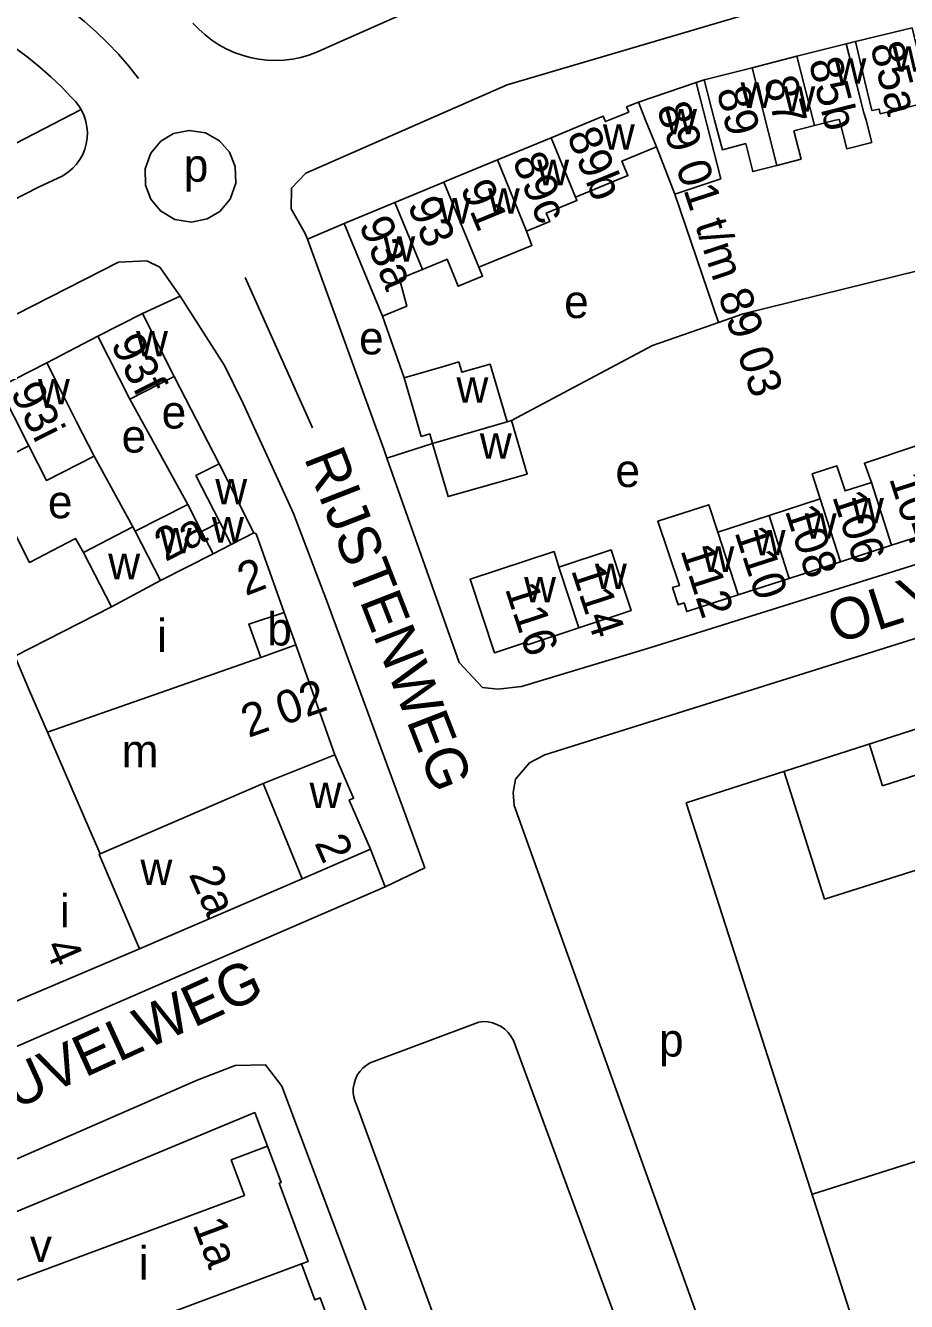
# Model space of a CAD drawing. Extents: x 157569 to 159501, y 382907 to 384670.
# Drawn here: x 158949.1 to 159055.8, y 383107 to 383261.5 of the extents above; entities that cross this region are included whole.
import ezdxf

# ---------------------------------------------------------------- set-up
doc = ezdxf.new("R2010")
doc.units = 0
for name, color, linetype in [('BLT_Basislijn', 7, 'Continuous'), ('BLT_Bebouwing', 7, 'Continuous'), ('BLT_Centroide', 7, 'Continuous'), ('BLT_Huisnummer', 7, 'Continuous'), ('BLT_Huisnummer_ tussenligend', 7, 'Continuous'), ('BLT_Huisnummer_reeks', 7, 'Continuous'), ('BLT_Onderverdeling_panden', 7, 'Continuous'), ('BLT_Straatnaam', 7, 'Continuous')]:
    doc.layers.add(name, color=color, linetype=linetype)

msp = doc.modelspace()

# ---------------------------------------------------------------- linework, layer by layer
at = {"layer": 'BLT_Basislijn'}
for p, q in [((158986.46, 383259.17), (158984.48, 383258.27)), ((159048.48, 383259.25), (159049.59, 383259.54)), ((159031.29, 383254.88), (159030.3, 383254.58)), ((158942.87, 383244.6), (158955.85, 383251.29)), ((158953.54, 383243.23), (158950.69, 383241.92)), ((159027.72, 383241.05), (159033.01, 383225.51)), ((158983.24, 383235.61), (158987.69, 383237.51)), ((158975.72, 383230.98), (158983.87, 383212.76)), ((158992.34, 383226.28), (158994.96, 383218.81)), ((158957.88, 383223.88), (158951.69, 383220.63)), ((158972.58, 383208.41), (158967.13, 383218.98)), ((158968.75, 383203.51), (158961.74, 383216.25)), ((158998.41, 383210.87), (158992.86, 383209.11)), ((158957.41, 383209.34), (158962.13, 383200.77)), ((159052.86, 383169.46), (159051.28, 383174.44)), ((159052.86, 383169.46), (159065.74, 383173.54)), ((159045.86, 383155.71), (159040.97, 383171.13)), ((159045.86, 383155.71), (159057.84, 383159.51)), ((158990.86, 383135.91), (159003.99, 383140.85)), ((159008.19, 383138.62), (159052.52, 383018.25)), ((159032.62, 383012.27), (158989.29, 383130.64)), ((159044.4, 383120.03), (159066.26, 383126.96))]:
    msp.add_line(p, q, dxfattribs=at)
for points in [[(158983.24, 383235.61), (158982.98, 383236.31), (158981.28, 383239.26), (158981.31, 383241.77), (158983.04, 383243.59), (159007.41, 383254.28), (159036.07, 383262.73), (159100, 383276.35), (159146.03, 383286.21), (159155.39, 383288.52), (159181.52, 383295.52), (159205.36, 383303.77), (159241.92, 383319.57), (159301.34, 383349.43)], [(159258.99, 383340.92), (159227.33, 383325.46), (159190.02, 383310.81), (159165.47, 383303.18), (159141.61, 383297.45), (159119.64, 383292.64), (159100, 383288.81), (159051.92, 383279.92), (159027.35, 383274.07), (158997.57, 383264.08), (158986.46, 383259.17)], [(158962.81, 383255.07), (158961.61, 383256.56), (158960.36, 383257.99), (158959.05, 383259.37), (158957.67, 383260.7), (158956.25, 383261.97), (158954.77, 383263.17), (158953.24, 383264.32), (158951.67, 383265.39), (158950.06, 383266.4), (158948.4, 383267.35), (158946.7, 383268.22), (158944.97, 383269.02), (158943.21, 383269.74), (158941.42, 383270.4), (158939.6, 383270.97), (158938.1, 383271.39)], [(158954.68, 383252.76), (158953.46, 383254.04), (158952.19, 383255.27), (158950.87, 383256.43), (158949.49, 383257.54), (158948.06, 383258.59), (158946.59, 383259.56), (158945.08, 383260.47), (158943.52, 383261.32), (158941.93, 383262.08), (158940.31, 383262.78), (158938.66, 383263.4), (158938.35, 383263.51)], [(158969.39, 383261.76), (158970.1, 383261.01), (158970.86, 383260.32), (158971.67, 383259.69), (158972.53, 383259.13), (158973.43, 383258.63), (158974.37, 383258.21), (158975.34, 383257.86), (158976.33, 383257.59), (158977.34, 383257.39), (158978.36, 383257.27), (158979.39, 383257.24), (158980.41, 383257.28), (158981.43, 383257.4), (158982.44, 383257.6), (158983.43, 383257.88), (158984.48, 383258.27)], [(158954.68, 383252.76), (158955.16, 383252.27), (158955.58, 383251.73), (158955.85, 383251.29)], [(158955.85, 383251.29), (158955.93, 383251.14), (158956.22, 383250.52), (158956.43, 383249.86), (158956.56, 383249.19), (158956.61, 383248.51), (158956.59, 383247.82), (158956.48, 383247.15), (158956.3, 383246.49), (158956.04, 383245.85), (158955.7, 383245.25), (158955.3, 383244.7), (158954.84, 383244.19), (158954.32, 383243.74), (158953.76, 383243.35), (158953.54, 383243.23)], [(158964.28, 383240.45), (158963.64, 383242.16), (158963.61, 383244.13), (158964.29, 383246.01), (158965.52, 383247.47), (158967.05, 383248.38), (158968.92, 383248.76), (158970.9, 383248.46), (158972.62, 383247.49), (158973.82, 383246.12)], [(158973.82, 383246.12), (158974.51, 383244.4), (158974.57, 383242.39), (158973.9, 383240.46), (158972.66, 383238.97), (158971.11, 383238.05), (158969.2, 383237.67), (158967.19, 383238), (158965.46, 383239.02), (158964.28, 383240.45)], [(158950.69, 383241.92), (158900.38, 383216.18), (158872.67, 383201.63), (158869.57, 383201.4), (158867.85, 383201.97), (158865.45, 383204.11), (158860.24, 383214.9), (158860.73, 383216.37)], [(158992.86, 383209.11), (158992.49, 383210.17), (158983.24, 383235.61)], [(159033.01, 383225.51), (159036.02, 383226.55), (159069.54, 383234.85), (159071.6, 383228.57)], [(158713.92, 383128.64), (158712.94, 383133.49), (158714.96, 383135.61), (158716, 383136.04), (158726.81, 383137.39), (158746.81, 383140.46), (158763.56, 383144.53), (158777.06, 383148.27), (158789.46, 383152.3), (158807.27, 383158.8), (158820.57, 383164.35), (158834.91, 383169.88), (158851.49, 383178.15), (158858.84, 383181.12), (158960.36, 383232.84), (158963.81, 383232.99), (158965.38, 383232.2), (158967.85, 383228.7)], [(158967.85, 383228.7), (158963.27, 383226.61)], [(158967.85, 383228.7), (158973.19, 383220.33), (158975.44, 383215.8), (158979.89, 383206.05), (158981.58, 383202.4), (158985.54, 383191.9), (158994.7, 383167.01), (158997.45, 383159.51), (158992.66, 383157.23)], [(159033.01, 383225.51), (159031.54, 383225), (159025.01, 383222.72), (159007.97, 383213.64)], [(158992.86, 383209.11), (159001.6, 383184.37), (159004.46, 383181.35), (159006.29, 383181.14), (159009.17, 383181.46), (159024.84, 383186.18), (159079.71, 383203.39)], [(158956.15, 383197.7), (158955.15, 383199.38), (158949.59, 383196.49), (158943.86, 383207.72)], [(159095.76, 383199.49), (159012.01, 383173.2), (159010.9, 383172.61)], [(159056.81, 383032.3), (159050.6, 383048.46), (159049.9, 383051.11), (159008.27, 383167.05), (159008.15, 383168.62), (159008.43, 383170.26), (159010.15, 383172.21), (159010.9, 383172.61)], [(158992.66, 383157.23), (158990.89, 383161.78)], [(158798.88, 383067.54), (158806.29, 383075.44), (158812.08, 383078.95), (158826.96, 383085.41), (158855.36, 383097.72), (158904.77, 383119.14), (158965.12, 383145.3), (158992.66, 383157.23)], [(159003.99, 383140.85), (159004.55, 383140.9), (159005.11, 383140.86), (159005.66, 383140.75), (159006.19, 383140.57), (159006.69, 383140.31), (159007.14, 383139.98), (159007.55, 383139.59), (159007.89, 383139.14), (159008.19, 383138.62)], [(158936.77, 383119.38), (158969.88, 383133.81), (158974.51, 383135.58), (158978.18, 383135.67), (158980.16, 383133.11), (159017.03, 383034.98), (159017.34, 383033.57), (159025.08, 383013.6), (159026.48, 383010.61), (159027.89, 383004.66), (159027.89, 382995.94), (159019.93, 382958.95)], [(158990.86, 383135.91), (158990.39, 383135.63), (158989.96, 383135.28), (158989.59, 383134.87), (158989.28, 383134.41), (158989.05, 383133.92), (158988.89, 383133.39), (158988.8, 383132.85), (158988.8, 383132.3), (158988.87, 383131.75), (158989.02, 383131.22), (158989.29, 383130.64)], [(158978.43, 383125.82), (158976.88, 383129.89), (158938.9, 383114.12)]]:
    msp.add_lwpolyline(points, dxfattribs=at)
msp.add_lwpolyline([(159029.12, 383167.37), (159059.9, 383071.66), (159120.99, 383091.31), (159090.21, 383187.01)], close=True, dxfattribs=at)
at = {"layer": 'BLT_Bebouwing'}
for p, q in [((159056.47, 383261.17), (159049.59, 383259.54)), ((159048.48, 383259.25), (159042.51, 383257.74)), ((159042.51, 383257.74), (159037.08, 383256.36)), ((159037.08, 383256.36), (159031.29, 383254.88)), ((159023.31, 383252.19), (159030.3, 383254.58)), ((159012.74, 383247.88), (159006.24, 383245.19)), ((159027.72, 383241.05), (159025.5, 383246.77)), ((158993.83, 383240.05), (158999.77, 383242.51)), ((158987.69, 383237.51), (158993.83, 383240.05)), ((158992.34, 383226.28), (158987.69, 383237.51)), ((158957.88, 383223.88), (158963.27, 383226.61)), ((158963.27, 383226.61), (158967.13, 383218.98)), ((158961.74, 383216.25), (158957.88, 383223.88)), ((158951.69, 383220.63), (158945.9, 383217.7)), ((158967.13, 383218.98), (158961.74, 383216.25)), ((158996.21, 383214.55), (158994.96, 383218.81)), ((158955.29, 383213.51), (158957.41, 383209.34)), ((159007.42, 383213.48), (159007.97, 383213.64)), ((158949.52, 383210.59), (158943.86, 383207.72)), ((158972.58, 383208.41), (158976.75, 383200.05)), ((159045.32, 383204.16), (159039.13, 383202.15)), ((159039.13, 383202.15), (159032.93, 383200.14)), ((158962.13, 383200.77), (158956.15, 383197.7)), ((158962.39, 383200.28), (158962.13, 383200.77)), ((159060.18, 383200.58), (159053.98, 383198.57)), ((159053.98, 383198.57), (159047.78, 383196.56)), ((158956.15, 383197.7), (158959.54, 383191.09)), ((159047.78, 383196.56), (159041.59, 383194.55)), ((159041.59, 383194.55), (159035.39, 383192.55)), ((158980.42, 383190.43), (158981.83, 383186.5)), ((158986.55, 383173.21), (158981.83, 383186.5)), ((158982.61, 383158.19), (158962.93, 383149.7))]:
    msp.add_line(p, q, dxfattribs=at)
for points in [[(159049.59, 383259.54), (159050.75, 383254.67), (159051.59, 383251.16), (159052.45, 383251.36), (159052.59, 383250.78), (159058.6, 383252.21), (159057.63, 383256.3), (159056.47, 383261.17)], [(159044.64, 383249.36), (159047.2, 383250), (159047.62, 383250.1), (159047.67, 383250), (159048.55, 383246.54), (159051.57, 383247.31), (159050.91, 383250), (159050.62, 383250.9), (159049.71, 383254.41), (159048.48, 383259.25)], [(159030.3, 383254.58), (159033.28, 383242.92), (159027.72, 383241.05)], [(159031.29, 383254.88), (159032.53, 383250), (159033.48, 383246.43), (159036.31, 383247.17), (159037.16, 383243.79), (159040.09, 383244.53)], [(159023.31, 383252.19), (159021.89, 383251.61), (159022.15, 383250.99), (159019.73, 383250), (159019.33, 383249.84), (159019.26, 383250), (159019.07, 383250.49), (159017.87, 383250), (159012.74, 383247.88)], [(159040.09, 383244.53), (159043.02, 383245.28), (159042.14, 383248.73), (159044.64, 383249.36)], [(159015.71, 383240.68), (159022.05, 383243.3), (159021.33, 383245.05), (159025.5, 383246.77)], [(158999.77, 383242.51), (159000, 383242.61), (159006.24, 383245.19)], [(159009.78, 383236.58), (159012.59, 383237.73), (159012.17, 383238.75), (159015.88, 383240.27), (159015.71, 383240.68)], [(159004.01, 383232.21), (159010.42, 383234.85), (159009.78, 383236.58)], [(158997.19, 383231.95), (159000, 383233.11), (159000.15, 383233.17), (159001.5, 383229.91), (159004.46, 383231.13), (159004.01, 383232.21)], [(158997.19, 383231.95), (158994.4, 383230.79), (158995.27, 383227.49), (158992.34, 383226.28)], [(158955.29, 383213.51), (158953.95, 383216.17), (158951.69, 383220.63)], [(158994.96, 383218.81), (159000, 383220.28), (159001.56, 383220.74), (159001.93, 383219.49), (159005.37, 383220.49), (159007.42, 383213.48)], [(158998.41, 383210.87), (158998.06, 383212.03), (158997.03, 383211.73), (158996.21, 383214.55)], [(159007.97, 383213.64), (159009.84, 383207.18), (159000.28, 383204.45), (159000, 383205.43), (158998.41, 383210.87)], [(158957.41, 383209.34), (158951.64, 383206.41), (158949.52, 383210.59)], [(159057, 383210.39), (159056.93, 383210.58), (159050.69, 383208.49), (159051.52, 383206.17)], [(158972.63, 383201.36), (158969.74, 383207), (158972.58, 383208.41)], [(159051.52, 383206.17), (159048.34, 383205.14), (159047.36, 383208.17), (159044.36, 383207.2), (159045.32, 383204.16)], [(158962.39, 383200.28), (158968.75, 383203.51)], [(158968.75, 383203.51), (158970.44, 383200.22)], [(159035.39, 383192.55), (159029.2, 383190.54), (159028.86, 383191.59), (159028.12, 383191.35), (159027.45, 383193.43), (159028.28, 383193.7), (159025.66, 383201.47), (159031.83, 383203.46), (159032.93, 383200.14)], [(158970.44, 383200.22), (158972.63, 383201.36)], [(158976.75, 383200.05), (158977.03, 383199.94), (158980.42, 383190.43)], [(159016.12, 383188.57), (159009.89, 383186.52), (159009.79, 383186.82), (159005.89, 383185.54), (159002.95, 383194.45), (159013.1, 383197.79), (159013.7, 383195.91)], [(159013.7, 383195.91), (159020.02, 383197.99), (159020.87, 383195.4), (159022.44, 383190.65), (159016.12, 383188.57)], [(158959.54, 383191.09), (158947.83, 383185.13)], [(158990.89, 383161.78), (158988.32, 383167.72), (158988.84, 383167.94), (158986.55, 383173.21)], [(158982.61, 383158.19), (158990.89, 383161.78)], [(158962.93, 383149.7), (158945.49, 383142.33), (158945.35, 383142.66), (158945.11, 383142.55)], [(158978.43, 383125.82), (158974.02, 383124.18), (158975.62, 383119.87), (158941.83, 383107.31)], [(158982.54, 383111.57), (158983.33, 383111.86), (158979.81, 383121.34), (158980.06, 383121.43), (158978.43, 383125.82)], [(158988.38, 383097.88), (158984.81, 383107.48), (158984.16, 383107.23), (158982.54, 383111.57)]]:
    msp.add_lwpolyline(points, dxfattribs=at)
at = {"layer": 'BLT_Onderverdeling_panden'}
for p, q in [((159044.64, 383249.36), (159042.51, 383257.74)), ((159040.09, 383244.53), (159037.08, 383256.36)), ((159015.71, 383240.68), (159012.74, 383247.88)), ((159009.78, 383236.58), (159006.24, 383245.19)), ((159004.01, 383232.21), (158999.77, 383242.51)), ((158997.19, 383231.95), (158993.83, 383240.05)), ((158949.52, 383210.59), (158945.9, 383217.7)), ((158998.41, 383210.87), (159007.42, 383213.48)), ((159053.98, 383198.57), (159051.52, 383206.17)), ((159047.78, 383196.56), (159045.32, 383204.16)), ((159041.59, 383194.55), (159039.13, 383202.15)), ((158970.44, 383200.22), (158971.83, 383197.52)), ((158974.03, 383198.64), (158976.75, 383200.05)), ((159035.39, 383192.55), (159032.93, 383200.14)), ((158974.03, 383198.64), (158971.83, 383197.52)), ((159016.12, 383188.57), (159013.7, 383195.91)), ((158959.54, 383191.09), (158965.46, 383194.29)), ((158977.6, 383184.96), (158981.83, 383186.5)), ((158977.6, 383184.96), (158951.76, 383175.93)), ((158977.88, 383169.74), (158986.55, 383173.21)), ((158958.17, 383161.23), (158977.88, 383169.74)), ((158977.88, 383169.74), (158982.61, 383158.19)), ((158956.78, 383164.37), (158958.17, 383161.23)), ((158962.93, 383149.7), (158958.21, 383160.75)), ((158982.54, 383111.57), (158945.86, 383097.96))]:
    msp.add_line(p, q, dxfattribs=at)
for points in [[(159025.5, 383246.77), (159024.17, 383250), (159023.31, 383252.19)], [(158974.03, 383198.64), (158972.63, 383201.36)], [(158962.39, 383200.28), (158965.46, 383194.29)], [(158965.46, 383194.29), (158971.83, 383197.52)], [(158980.42, 383190.43), (158976.15, 383189.01), (158977.6, 383184.96)], [(158947.83, 383185.13), (158949.61, 383180.96)], [(158949.61, 383180.96), (158951.76, 383175.93)], [(158951.76, 383175.93), (158956.78, 383164.37)], [(158958.17, 383161.23), (158958.05, 383161.18), (158958.21, 383160.75)]]:
    msp.add_lwpolyline(points, dxfattribs=at)

# ---------------------------------------------------------------- texts
at = {"layer": 'BLT_Centroide'}
for s, p in [('w', (159054.09, 383255.86)), ('w', (159047.05, 383254.42)), ('w', (159035.69, 383251.5)), ('w', (159040.86, 383251.02)), ('w', (159026.55, 383248.3)), ('w', (159019.02, 383246.44)), ('p', (158968.28, 383242.56)), ('w', (159011.06, 383242.14)), ('w', (159005.09, 383238.69)), ('w', (158999.14, 383237.5)), ('w', (158992.44, 383232.89)), ('e', (159014.33, 383226.06)), ('w', (158962.5, 383221.44)), ('e', (158989.5, 383221.66)), ('w', (158950.62, 383215.62)), ('w', (159001.29, 383215.81)), ('e', (158965.6, 383212.69)), ('e', (158960.75, 383209.78)), ('w', (159004.12, 383209.03)), ('e', (159020.54, 383205.61)), ('w', (158972.09, 383203.52)), ('e', (158951.83, 383201.83)), ('w', (159049.17, 383201.2)), ('w', (158971.69, 383198.89)), ('w', (159043.45, 383199.36)), ('w', (158965.38, 383197.59)), ('w', (159037.27, 383197.34)), ('w', (159031.06, 383195.34)), ('w', (158959.13, 383194.45)), ('w', (159018.06, 383193.28)), ('w', (159009.48, 383191.66)), ('b', (158978.39, 383186.43)), ('i', (158965.06, 383185.63)), ('m', (158960.76, 383171.68)), ('w', (158983.51, 383166.74)), ('w', (158963.03, 383157.44)), ('i', (158953.29, 383152.31)), ('p', (159025.82, 383136.68)), ('v', (158949.65, 383111.82)), ('i', (158962.84, 383109.69))]:
    msp.add_text(s, height=4, dxfattribs=at).set_placement(p)
at = {"layer": 'BLT_Huisnummer'}
for s, rotation, p in [('85a', 284.2559, (159051.36, 383259.01)), ('85b', 284.2629, (159043.91, 383257.11)), ('87', 284.2629, (159038.48, 383254.85)), ('89', 284.2597, (159032.76, 383253.6)), ('89b', 292.3893, (159014.6, 383248.19)), ('89c', 292.3922, (159008, 383245.16)), ('91', 292.3889, (159001.71, 383241.83)), ('93', 292.4996, (158995.31, 383239.79)), ('93a', 292.5075, (158989.43, 383237.4)), ('93f', 296.8528, (158959.36, 383222.93)), ('93i', 296.8746, (158947.22, 383217.1)), ('106', 287.9516, (159046.76, 383204.48)), ('2a', 27.1927, (158966.06, 383196.51)), ('112', 287.9494, (159028.37, 383197.97)), ('2', 21.4137, (158975.77, 383192.38)), ('114', 288.224, (159015.15, 383195.55)), ('116', 288.224, (159007.13, 383193.32)), ('2', 293.4438, (158984.06, 383162.54)), ('4', 293.4466, (158951.35, 383149.99)), ('1a', 290.3913, (158969.31, 383116.36))]:
    msp.add_text(s, height=4, rotation=rotation, dxfattribs=at).set_placement(p)
at = {"layer": 'BLT_Huisnummer_ tussenligend'}
for s, rotation, p in [('104', 287.9494, (159053.64, 383206.66)), ('108', 287.9516, (159041.02, 383202.77)), ('110', 287.9516, (159034.93, 383200.16))]:
    msp.add_text(s, height=4, rotation=rotation, dxfattribs=at).set_placement(p)
at = {"layer": 'BLT_Huisnummer_reeks'}
for s, rotation, p in [('89 01 t/m 89 03', 288.2597, (159025.48, 383251.49)), ('2 02', 19.4438, (158976.1, 383175.23)), ('2a', 293.4438, (158968.85, 383158.74))]:
    msp.add_text(s, height=4, rotation=rotation, dxfattribs=at).set_placement(p)
at = {"layer": 'BLT_Straatnaam'}
for s, height, rotation, p in [('RIJSTENWEG', 5, 291.2734, (158982.8, 383209.15)), ('OLYMPIALAAN', 5, 17.7421, (159047.23, 383186.61)), ('SPEELHEUVELWEG', 4.9999, 24.5656, (158919.81, 383117.42))]:
    msp.add_text(s, height=height, rotation=rotation, dxfattribs=at).set_placement(p)

doc.saveas('drawing.dxf')
